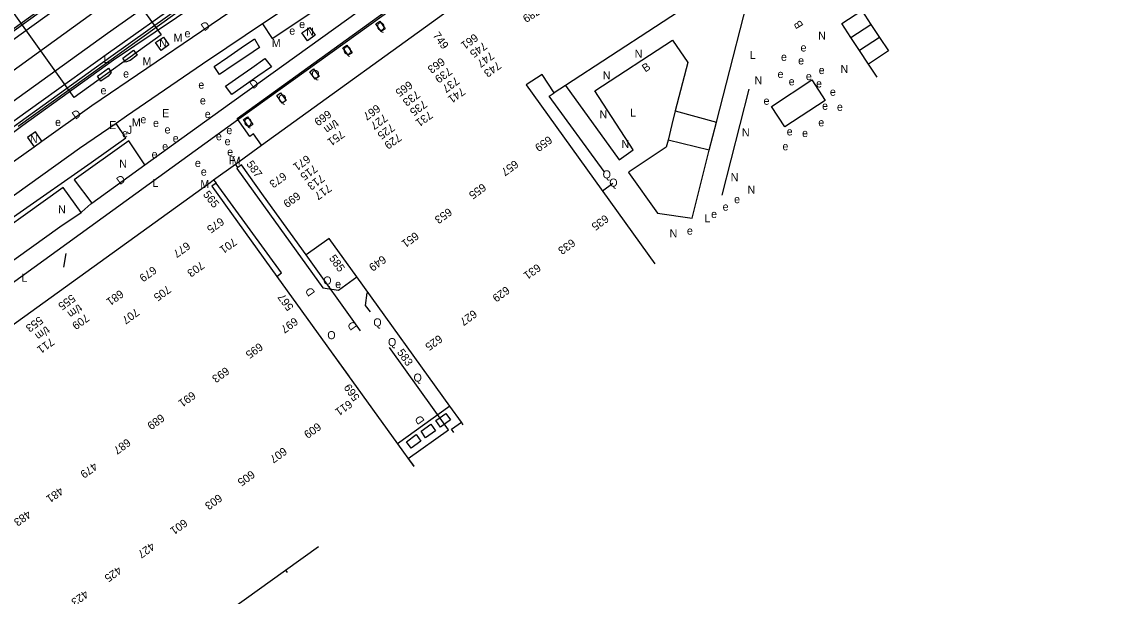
# Model space of a CAD drawing. Extents: x 81617 to 82144, y 454649 to 455150.
# Drawn here: x 81980 to 82116, y 454892.9 to 454964.6 of the extents above; entities that cross this region are included whole.
import ezdxf

# ---------------------------------------------------------------- set-up
doc = ezdxf.new("R2010")
doc.units = 0
doc.layers.add('B-WE-OG-TOPOGRAFIE-G', color=7, linetype='Continuous')
doc.layers.add('B-WE-VW-MARKERING-G', color=7, linetype='Continuous')

msp = doc.modelspace()

# ---------------------------------------------------------------- linework, layer by layer
at = {"layer": 'B-WE-OG-TOPOGRAFIE-G'}
for p, q in [((82028.02, 454976.37), (82010.03, 454964.3)), ((81989.05, 454974.53), (81997.37, 454962.91)), ((82071.54, 454972.04), (82047.89, 454956.61)), ((82006.85, 454952.47), (82033.01, 454971.38)), ((81986.5, 454955.11), (81978.16, 454966.74)), ((82082.38, 454964.33), (82084.88, 454965.98)), ((82084.88, 454965.98), (82086.03, 454964.22)), ((82083.52, 454962.61), (82082.38, 454964.33)), ((82083.52, 454962.61), (82086.03, 454964.22)), ((82086.03, 454964.22), (82087.11, 454962.59)), ((81997.37, 454962.91), (81986.5, 454955.11)), ((82084.6, 454960.97), (82083.52, 454962.61)), ((82087.11, 454962.59), (82084.6, 454960.97)), ((82085.71, 454959.28), (82084.6, 454960.97)), ((82003.34, 454959.82), (81993.02, 454952.78)), ((82063.15, 454959.49), (82061.59, 454953.46)), ((82086.81, 454957.65), (82085.71, 454959.28)), ((82045.85, 454955.26), (82046.44, 454955.67)), ((82047.89, 454956.61), (82054.59, 454947.31)), ((82070.76, 454956.15), (82067.41, 454942.93)), ((82052.69, 454945.86), (82045.85, 454955.26)), ((81993.02, 454952.78), (81991.75, 454951.88)), ((82061.59, 454953.46), (82066.72, 454952.02)), ((82007.37, 454952.59), (81950.92, 454911.81)), ((82008.46, 454950.24), (82006.85, 454952.47)), ((82065.81, 454948.53), (82066.72, 454952.02)), ((82008.9, 454950.55), (82008.46, 454950.24)), ((82009.92, 454949.17), (82008.9, 454950.55)), ((81976.85, 454945.66), (81981.5, 454948.96)), ((81981.5, 454948.96), (81982.48, 454949.66)), ((82065.81, 454948.53), (82060.69, 454949.77)), ((81988.69, 454941.92), (81995.34, 454946.7)), ((82003.91, 454944.83), (82006.65, 454946.8)), ((82006.96, 454946.37), (82006.65, 454946.8)), ((82003.91, 454944.83), (82004.22, 454944.4)), ((82053.79, 454944.35), (82052.51, 454943.43)), ((81985.46, 454935.63), (81985.17, 454933.93)), ((82022.27, 454925.98), (82015.49, 454935.46)), ((82011.8, 454932.76), (82026.88, 454911.87)), ((82033.42, 454916.59), (82021.82, 454932.7)), ((82022.89, 454929.16), (82023.09, 454930.74)), ((82023.52, 454928.33), (82022.89, 454929.16)), ((82018.62, 454923.37), (82020.83, 454920.3)), ((82033.25, 454913.62), (82025.9, 454923.91)), ((82033.42, 454916.59), (82026.88, 454911.87)), ((82034.87, 454914.57), (82033.42, 454916.59)), ((82028.23, 454910.03), (82033.25, 454913.62)), ((82035.1, 454914.26), (82034.87, 454914.57)), ((82026.88, 454911.87), (82028.91, 454909.06)), ((82028.23, 454910.03), (82028.91, 454909.07)), ((82012.9, 454896.12), (82017, 454899.07)), ((82004.5, 454890.06), (82012.9, 454896.12)), ((82012.9, 454896.12), (82013.12, 454895.82))]:
    msp.add_line(p, q, dxfattribs=at)
for points in [[(81908.89, 454909.67), (81922.08, 454920.43), (81934.06, 454929.94), (81952.81, 454944.44), (81970.93, 454957.96), (81989.89, 454971.63), (82009.08, 454984.97), (82010.71, 454986.08), (82028.88, 454998.27), (82047.26, 455010.14), (82051.22, 455012.63), (82070.77, 455024.75), (82077.17, 455028.65), (82100.03, 455042.05), (82099.93, 455042.25), (82105.5, 455045.47), (82101.82, 455050.38), (82106.42, 455053.06)], [(82110.86, 455047.25), (82106.6, 455044.53), (82093.16, 455036.79), (82086.19, 455032.73), (82077.78, 455027.74), (82071.32, 455023.81), (82051.79, 455011.7), (82032.01, 454998.95), (82011.35, 454985.19), (81991.43, 454971.34), (81971.57, 454957.06), (81953.64, 454943.68), (81934.75, 454929.1), (81934.67, 454929.06), (81923.98, 454920.56)], [(82110.86, 455047.25), (82106.6, 455044.53), (82093.16, 455036.79), (82086.19, 455032.73), (82077.78, 455027.74), (82071.32, 455023.81), (82051.79, 455011.7), (82032.01, 454998.95), (82011.35, 454985.19), (81991.43, 454971.34), (81971.57, 454957.06), (81953.64, 454943.68), (81934.75, 454929.1), (81934.67, 454929.06), (81923.98, 454920.56)], [(82114.39, 455042.64), (82109.71, 455039.76), (82081.51, 455022.6), (82074.64, 455018.41), (82055.67, 455006.7), (82036.92, 454994.66), (82036.45, 454994.35), (82018.57, 454982.51), (82000.9, 454970.34), (81999.11, 454969.08), (81990.68, 454963.1), (81977.83, 454953.85), (81958.78, 454939.67), (81938.84, 454924.35), (81924.75, 454913.11), (81914.04, 454904.32)], [(82115.7, 455040.92), (82082.53, 455020.83), (82075.64, 455016.65), (82054.28, 455003.39), (82037.55, 454992.67), (82017.62, 454979.37), (82000.31, 454967.43), (81990.77, 454960.65), (81979.42, 454952.47), (81977.59, 454951.14), (81958.71, 454937.07), (81940.07, 454922.69), (81926.19, 454911.63), (81915.47, 454902.83)], [(82116.04, 455040.48), (82082.82, 455020.36), (82075.93, 455016.18), (82054.58, 455002.93), (82037.85, 454992.21), (82017.93, 454978.92), (82000.63, 454966.98), (81991.09, 454960.2), (81979.74, 454952.03), (81977.91, 454950.69), (81959.04, 454936.63), (81940.4, 454922.26), (81926.53, 454911.2), (81915.85, 454902.44)], [(82083.03, 455019.96), (82057.18, 455003.95), (81991.41, 454959.77), (81980.08, 454951.61), (81979.41, 454951.12), (81959.96, 454936.64), (81940.76, 454921.84), (81926.02, 454909.68), (81916.31, 454901.96)], [(82010.03, 454964.3), (82011.22, 454962.46), (82034.62, 454978.05), (82057.64, 454993.13), (82057.08, 454994), (82077.14, 455006.54), (82076.26, 455008.02)], [(82084.42, 455004.39), (82073.51, 454997.28), (82033.93, 454971.56), (82033.72, 454971.44), (82029.8, 454968.76), (82007.37, 454952.59)], [(82006.65, 454946.8), (82009.92, 454949.17), (82035.19, 454967.44), (82083.36, 454998.28), (82083.52, 454998.07)], [(82041.44, 454994.17), (82038.15, 454992.04), (82018.28, 454978.79), (81999.08, 454965.52), (81979.5, 454951.5)], [(82009.23, 454984.74), (81990.03, 454971.4), (81971.07, 454957.73), (81952.96, 454944.21), (81934.2, 454929.71), (81934.03, 454929.93), (81922.08, 454920.43), (81921.76, 454920.18), (81908.89, 454909.67)], [(81995.34, 454946.7), (82004.86, 454953.56), (82028.33, 454970.48), (82032.5, 454973.33), (82034.95, 454974.92)], [(82066.72, 454952.02), (82071.77, 454971.72), (82071.54, 454972.04)], [(81982.48, 454949.66), (81988.72, 454954.1), (82009.32, 454968.11)], [(82010.03, 454964.3), (82003.39, 454959.84), (82003.34, 454959.82)], [(82014.95, 454963.16), (82015.92, 454963.86), (82016.61, 454962.89), (82015.65, 454962.19), (82014.95, 454963.16)], [(82024.68, 454964.63), (82025.36, 454963.67), (82024.86, 454963.35), (82024.2, 454964.29), (82024.68, 454964.63)], [(81998.34, 454961.66), (81997.35, 454960.98), (81996.68, 454961.97), (81997.67, 454962.65), (81998.34, 454961.66)], [(82009.67, 454961.35), (82008.07, 454960.27), (82006.37, 454959.15), (82004.64, 454957.96), (82003.99, 454958.98), (82005.69, 454960.14), (82007.34, 454961.3), (82009.02, 454962.43), (82009.67, 454961.35)], [(82087.11, 454962.59), (82088.21, 454960.92), (82085.71, 454959.28)], [(81992.93, 454959.51), (81992.56, 454960.02), (81993.93, 454961.01), (81994.39, 454960.38), (81993.5, 454959.72), (81992.93, 454959.51)], [(82020.55, 454961.65), (82021.23, 454960.69), (82020.74, 454960.37), (82020.07, 454961.31), (82020.55, 454961.65)], [(82054.59, 454947.31), (82056.32, 454948.57), (82051.53, 454955.94), (82061.26, 454962.27), (82063.15, 454959.49)], [(82011.13, 454958.92), (82009.46, 454957.75), (82006.19, 454955.46), (82005.39, 454956.5), (82007.05, 454957.67), (82008.68, 454958.82), (82010.33, 454959.98), (82011.13, 454958.92)], [(81991.14, 454958.23), (81990.76, 454957.77), (81989.85, 454957.13), (81989.4, 454957.77), (81990.78, 454958.75), (81991.14, 454958.23)], [(82016.41, 454958.67), (82017.1, 454957.71), (82016.6, 454957.39), (82015.93, 454958.32), (82016.41, 454958.67)], [(82047.89, 454956.61), (82046.44, 454955.67), (82044.94, 454957.97), (82042.96, 454956.68), (82059.05, 454934.36)], [(82080.29, 454954.75), (82075.26, 454951.45), (82073.61, 454953.97), (82078.63, 454957.29), (82080.29, 454954.75)], [(82012.28, 454955.68), (82012.97, 454954.72), (82012.47, 454954.4), (82011.81, 454955.34), (82012.28, 454955.68)], [(82061.59, 454953.46), (82061.17, 454951.74), (82060.69, 454949.77)], [(81950.79, 454922.31), (81952.12, 454920.57), (81961.15, 454927.3), (81979.35, 454940.48), (81988.62, 454947.01), (81992.94, 454950.06), (81991.75, 454951.88)], [(81991.75, 454951.88), (81987.15, 454948.72), (81963.65, 454931.88), (81959.86, 454929.12), (81950.79, 454922.31)], [(82008.15, 454952.7), (82008.83, 454951.74), (82008.33, 454951.42), (82007.67, 454952.36), (82008.15, 454952.7)], [(81982.48, 454949.66), (81981.67, 454950.8), (81980.69, 454950.1), (81981.5, 454948.96)], [(81995.34, 454946.7), (81993.33, 454949.7), (81986.49, 454944.82), (81988.69, 454941.92)], [(82060.69, 454949.77), (82060.46, 454948.9), (82055.83, 454945.81), (82055.73, 454945.74)], [(82055.73, 454945.74), (82059.38, 454940.68), (82063.71, 454940.06), (82065.81, 454948.53)], [(82006.96, 454946.37), (82006.81, 454946.25), (82017.55, 454931.33), (82019.51, 454931.04), (82021.82, 454932.7)], [(82015.49, 454935.46), (82010.17, 454942.85), (82010.16, 454942.85), (82007.4, 454946.68), (82006.96, 454946.37)], [(81952.52, 454907.79), (82003.49, 454944.5), (82003.91, 454944.83)], [(81987.37, 454940.77), (81985.11, 454943.86), (81973.45, 454935.55), (81975.66, 454932.49)], [(82004.22, 454944.4), (82003.7, 454944.02), (82011.8, 454932.76)], [(82011.8, 454932.76), (82012.41, 454933.2), (82004.22, 454944.4)], [(81987.37, 454940.77), (81987.45, 454940.83), (81988.57, 454941.83), (81988.69, 454941.92)], [(81975.66, 454932.49), (81984.71, 454938.98), (81987.37, 454940.77)], [(82021.82, 454932.7), (82018.35, 454937.52), (82015.49, 454935.46)], [(82032.28, 454913.97), (82031.69, 454914.78), (82032.91, 454915.66), (82033.49, 454914.85), (82032.28, 454913.97)], [(82030.4, 454912.63), (82029.83, 454913.44), (82031.04, 454914.31), (82031.62, 454913.51), (82030.4, 454912.63)], [(82033.94, 454913.29), (82033.65, 454913.7), (82034.87, 454914.57)], [(82029.82, 454912.21), (82028.61, 454911.33), (82028.03, 454912.14), (82029.24, 454913.02), (82029.82, 454912.21)]]:
    msp.add_lwpolyline(points, dxfattribs=at)
at = {"layer": 'B-WE-VW-MARKERING-G'}
msp.add_lwpolyline([(81923.98, 454920.56), (81953.27, 454939.42), (81956.88, 454942.19), (81975.97, 454956.39), (81988.85, 454965.67), (81997.29, 454971.66), (81999.1, 454972.93), (82016.8, 454985.13), (82034.71, 454996.99), (82035.2, 454997.3), (82053.99, 455009.37), (82072.99, 455021.1), (82079.58, 455025.12), (82111.52, 455043.93), (82112.79, 455044.73)], dxfattribs=at)

# ---------------------------------------------------------------- texts
at = {"layer": 'B-WE-OG-TOPOGRAFIE-G'}
for s, rotation, p in [('789', 212.631, (82044.3, 454966.44)), ('D', 34.2394, (82002.77, 454963.34)), ('B', 120.9677, (82077.62, 454964.08)), ('749', 305.8841, (82031.24, 454962.84)), ('661', 215.8711, (82036.51, 454963.15)), ('745', 215.8711, (82037.63, 454962.11)), ('663', 215.8711, (82032.36, 454960.15)), ('747', 215.8711, (82038.51, 454960.89)), ('739', 215.8711, (82033.26, 454958.95)), ('743', 215.8711, (82039.38, 454959.67)), ('B', 33.7031, (82057.85, 454958.22)), ('D', 35.7736, (82008.86, 454956.13)), ('665', 215.8711, (82028.33, 454957.24)), ('737', 215.8711, (82034.17, 454957.75)), ('733', 215.8711, (82029.25, 454956.05)), ('741', 215.8711, (82034.89, 454956.42)), ('667', 215.8711, (82024.29, 454954.31)), ('735', 215.8711, (82030.13, 454954.84)), ('D', 35.4091, (81986.67, 454952.32)), ('669', 215.8711, (82018.18, 454953.6)), ('727', 215.8711, (82025.21, 454953.13)), ('731', 215.8711, (82030.84, 454953.49)), ('t/m', 215.8711, (82019.1, 454952.41)), ('725', 215.8711, (82026.09, 454951.91)), ('751', 215.8711, (82019.83, 454951.09)), ('729', 215.8711, (82026.95, 454950.68)), ('659', 215.7414, (82045.76, 454950.38)), ('671', 215.8711, (82015.55, 454947.99)), ('587', 305.7383, (82007.96, 454946.79)), ('715', 215.8711, (82016.45, 454946.79)), ('657', 215.7414, (82041.54, 454947.35)), ('D', 35.7539, (81992.23, 454944.15)), ('673', 215.8721, (82012.59, 454945.85)), ('713', 215.8711, (82017.33, 454945.58)), ('565', 308.2604, (82002.54, 454942.98)), ('699', 215.8721, (82014.31, 454943.39)), ('717', 215.8711, (82018.21, 454944.36)), ('655', 215.7414, (82037.51, 454944.45)), ('653', 215.7414, (82033.25, 454941.38)), ('675', 215.7633, (82004.78, 454940.19)), ('635', 215.8348, (82052.82, 454940.54)), ('651', 215.7414, (82029.1, 454938.39)), ('677', 215.7633, (82000.55, 454937.15)), ('701', 215.7633, (82006.37, 454937.64)), ('633', 215.8348, (82048.65, 454937.53)), ('585', 305.9079, (82018.28, 454935.03)), ('649', 215.7414, (82025.02, 454935.45)), ('679', 215.7633, (81996.35, 454934.12)), ('703', 215.7633, (82002.32, 454934.72)), ('631', 215.8348, (82044.34, 454934.42)), ('681', 215.7633, (81992.23, 454931.15)), ('705', 215.7633, (81998.14, 454931.71)), ('D', 125.7407, (82016.64, 454930.75)), ('629', 215.8348, (82040.45, 454931.61)), ('555', 215.988, (81986.2, 454930.6)), ('567', 126.1531, (82013.97, 454928.94)), ('t/m', 215.988, (81987.06, 454929.37)), ('707', 215.7633, (81994.18, 454928.86)), ('627', 215.8348, (82036.37, 454928.66)), ('553', 215.9, (81982.16, 454927.85)), ('709', 215.988, (81987.94, 454928.16)), ('697', 215.8649, (82014.01, 454927.72)), ('D', 125.7571, (82021.92, 454926.51)), ('t/m', 215.9, (81983.01, 454926.62)), ('711', 215.9, (81983.57, 454925.17)), ('695', 215.8649, (82009.62, 454924.55)), ('625', 215.8348, (82032.05, 454925.54)), ('583', 305.9079, (82026.78, 454923.28)), ('693', 215.8649, (82005.43, 454921.53)), ('569', 125.5594, (82022.23, 454917.66)), ('691', 215.8649, (82001.23, 454918.48)), ('611', 215.77, (82020.8, 454917.39)), ('689', 215.8649, (81997.34, 454915.67)), ('D', 125.7594, (82030.33, 454914.75)), ('609', 215.77, (82016.9, 454914.58)), ('687', 215.8154, (81993.11, 454912.6)), ('607', 215.77, (82012.63, 454911.51)), ('479', 215.8154, (81988.97, 454909.61)), ('605', 215.77, (82008.62, 454908.62)), ('481', 215.8154, (81984.71, 454906.54)), ('603', 215.77, (82004.54, 454905.67)), ('483', 215.8154, (81980.67, 454903.63)), ('601', 215.7403, (82000.2, 454902.55)), ('427', 215.7403, (81996.13, 454899.63)), ('425', 215.7403, (81991.99, 454896.64)), ('423', 215.7403, (81987.84, 454893.66))]:
    msp.add_text(s, height=1, rotation=rotation, dxfattribs=at).set_placement(p)
for s, p in [('e', (82013.37, 454962.95)), ('e', (82014.6, 454963.77)), ('N', (82015.47, 454962.83)), ('Q', (82024.28, 454963.47)), ('N', (81997.13, 454961.39)), ('M', (81998.91, 454962.07)), ('e', (82000.28, 454962.62)), ('M', (82011.18, 454961.4)), ('N', (82079.43, 454962.34)), ('Q', (82020.11, 454960.47)), ('N', (82056.52, 454960.06)), ('e', (82077.23, 454960.85)), ('L', (81990.17, 454959.42)), ('M', (81995.03, 454959.13)), ('L', (82070.88, 454959.91)), ('e', (82074.79, 454959.67)), ('e', (82076.93, 454959.23)), ('e', (81992.61, 454957.59)), ('Q', (82016.12, 454957.52)), ('N', (82052.53, 454957.37)), ('e', (82074.36, 454957.54)), ('e', (82079.5, 454958.03)), ('N', (82082.22, 454958.17)), ('e', (82002.01, 454956.2)), ('N', (82071.48, 454956.75)), ('e', (82075.75, 454956.62)), ('e', (82077.9, 454957.27)), ('e', (82079.17, 454956.36)), ('e', (81989.79, 454955.5)), ('Q', (82011.99, 454954.47)), ('e', (82080.9, 454955.32)), ('e', (82002.2, 454954.24)), ('e', (82072.61, 454954.2)), ('e', (82079.92, 454953.57)), ('e', (82081.78, 454953.43)), ('E', (81997.48, 454952.65)), ('e', (82002.81, 454952.55)), ('N', (82052.12, 454952.5)), ('L', (82055.96, 454952.72)), ('e', (81984.11, 454951.54)), ('E', (81990.87, 454951.16)), ('J', (81993.09, 454950.57)), ('M', (81993.71, 454951.49)), ('e', (81994.77, 454951.88)), ('e', (81996.35, 454951.42)), ('e', (81997.79, 454950.61)), ('Q', (82007.69, 454951.52)), ('e', (82079.45, 454951.5)), ('N', (81980.98, 454949.43)), ('e', (81992.48, 454950.13)), ('e', (81998.81, 454949.52)), ('e', (82004.21, 454949.77)), ('e', (82005.51, 454950.53)), ('N', (82069.91, 454950.24)), ('e', (82075.5, 454950.37)), ('e', (82077.42, 454950.17)), ('e', (81997.49, 454948.52)), ('e', (82005.29, 454949.15)), ('N', (82054.86, 454948.81)), ('e', (82074.97, 454948.52)), ('N', (81992.13, 454946.34)), ('e', (81996.17, 454947.52)), ('e', (82005.61, 454947.83)), ('F', (82005.83, 454946.78)), ('M', (82006.17, 454946.7)), ('e', (82001.58, 454946.43)), ('e', (82002.32, 454945.35)), ('Q', (82052.51, 454945.01)), ('L', (81996.27, 454943.94)), ('M', (82002.26, 454943.81)), ('Q', (82053.34, 454943.98)), ('N', (82068.51, 454944.66)), ('N', (82070.61, 454943.09)), ('e', (82068.93, 454941.91)), ('N', (81984.49, 454940.64)), ('L', (82065.22, 454939.54)), ('e', (82066.06, 454940.06)), ('e', (82067.5, 454940.98)), ('N', (82060.88, 454937.63)), ('e', (82063.04, 454937.98)), ('L', (81979.92, 454932.1)), ('Q', (82017.61, 454931.76)), ('e', (82019.1, 454931.32)), ('Q', (82023.87, 454926.53)), ('O', (82018.12, 454924.94)), ('Q', (82025.7, 454924.07)), ('Q', (82028.89, 454919.64))]:
    msp.add_text(s, height=1, dxfattribs=at).set_placement(p)

doc.saveas('drawing.dxf')
